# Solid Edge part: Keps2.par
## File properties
Author: KULL
Template: Iso Metric Part.par
Last saved by: KULL
Revision: 10
Application: Solid Edge
Accuracy: 0,990
Face Style: Model Default
Fill Style: Normal
Coef. of Thermal Exp: 0.0
Thermal Conductivity: 0.0
Specific Heat: 0.0
Modulus of Elasticity: 0.0
Poisson's Ratio: 0.0
Yield Stress: 0.0
Ultimate Stress: 0.0
Elongation: 0.0
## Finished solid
Body 1: solid body, 94 faces, 208 edges, 116 vertices.
  Faces by surface: cylinder 40, torus 36, plane 14, blend 4
  Edges by curve: circle 132, line 68, intersection 8
Bounding box of the edges (mm; curved faces can reach further): 4.159 x 24.282 x 27.404, from (-38, -24.4241, 39.7922) to (-33.841, -0.1423, 67.1961).
Cylindrical faces by radius (mm): R0.4 x20, R1 x8, R1.5 x1, R2 x7, R3 x1, R5 x1, R10 x2
Toroidal faces (ring radius, tube radius in mm): R0.6 r0.4 x6, R1.4 r0.4 x10, R1.6 r0.4 x4, R2.4 r0.4 x8, R2.6 r0.4 x2, R4.6 r0.4 x2, R9.6 r0.4 x2, R10.4 r0.4 x2
Planar faces by outward normal: +x 3, -x 3, oblique 8
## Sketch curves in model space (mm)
line (-35, -12.4628, 53.5146) -> (-35, -18.7293, 60.984)
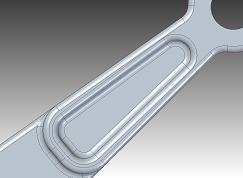
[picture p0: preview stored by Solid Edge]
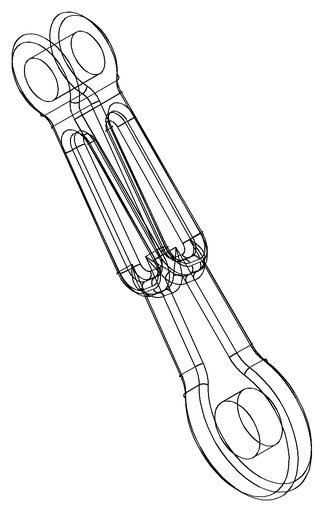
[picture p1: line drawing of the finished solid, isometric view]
